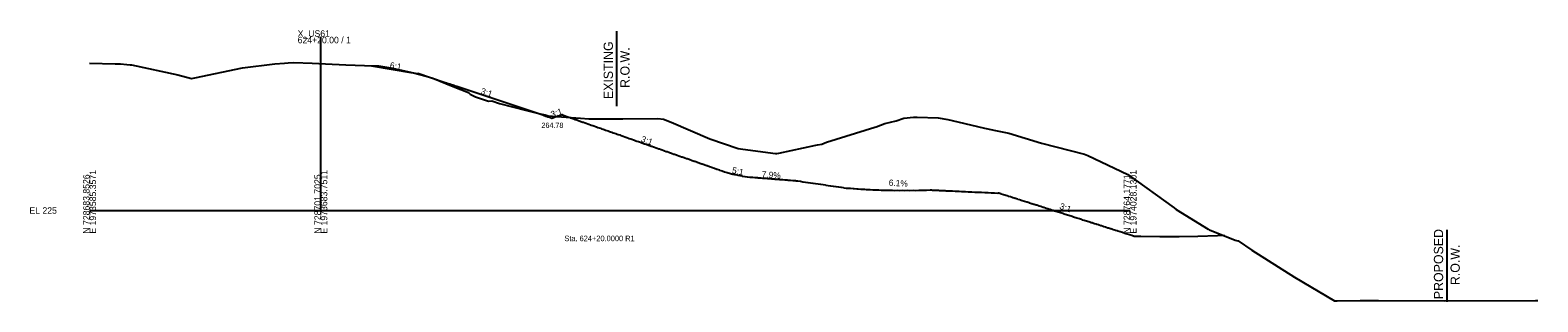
# Model space of a CAD drawing. Extents: x -26 to 630, y -39 to 9098.
# Drawn here: x -26 to 626, y 461 to 578 of the extents above; entities that cross this region are included whole.
import ezdxf

# ---------------------------------------------------------------- set-up
doc = ezdxf.new("R2010")
doc.units = 0
for name, color, linetype in [('CONST_DCH', 7, 'Continuous'), ('Default', 7, 'Continuous'), ('Draft_XS_Grid', 7, 'Continuous'), ('Draft_XS_Text', 7, 'Continuous'), ('DTM CONTOURS_MAJOR', 7, 'Continuous'), ('DTM_X_FLOW_ARROWS', 7, 'Continuous'), ('DTM_X_GROUND', 7, 'Continuous'), ('X_DTM_CONTOURS_MAJOR', 7, 'Continuous'), ('XS_CELL', 7, 'Continuous'), ('XS_P_GROUND', 7, 'Continuous'), ('XS_P_ROW', 7, 'Continuous'), ('XS_P_TX_DCH', 7, 'Continuous'), ('XS_P_TX_FS_BS', 7, 'Continuous'), ('XS_X_ROW', 7, 'Continuous')]:
    doc.layers.add(name, color=color, linetype=linetype)

msp = doc.modelspace()

# ---------------------------------------------------------------- linework, layer by layer
at = {"layer": 'DTM_X_GROUND'}
msp.add_lwpolyline([(0, 563.66), (11.1, 563.34), (13.43, 563.27), (16.14, 563.05), (17.6, 562.92), (18.16, 562.86), (38.23, 558.55), (44.07, 557.03), (45.47, 557.34), (66.13, 561.58), (80.12, 563.28), (84.36, 563.68), (85.9, 563.74), (88.33, 563.84), (96.23, 563.57), (102.11, 563.36), (110.84, 562.96), (122.88, 562.41), (123.55, 562.45), (125.17, 562.51), (130.34, 561.53), (140.05, 559.47), (145.65, 557.95), (148.53, 557.16), (157.2, 553.58), (163.95, 550.88), (164.61, 550.26), (166.94, 549.06), (172.54, 547.24), (174.02, 547.39), (177.3, 546.24), (188.5, 543.35), (194.95, 541.78), (197.02, 541.35), (198.38, 540.8), (202.11, 540.54), (212.35, 539.83), (215.89, 539.57), (223.5, 539.54), (226.67, 539.6), (227.21, 539.54), (230.69, 539.6), (245.81, 539.77), (248.27, 539.36), (251.61, 538.09), (268.33, 531), (280.45, 526.82), (281.46, 526.69), (291.23, 525.37), (296.62, 524.67), (297.28, 524.57), (298.08, 524.81), (314.15, 528.25), (314.84, 528.29), (316.73, 528.66), (318.77, 529.53), (339.61, 536.02), (340.19, 536.17), (343.92, 537.62), (348.86, 538.67), (352.14, 539.81), (356.33, 540.26), (357.98, 540.35), (367.03, 539.99), (367.03, 539.99), (371.19, 539.26), (375.53, 538.32), (387.04, 535.56), (387.73, 535.42), (391.84, 534.55), (397.54, 533.33), (411.74, 529.05), (430.32, 524.26), (431.77, 523.79), (449, 515.57), (469.04, 501.19), (470.02, 500.38), (483.78, 491.87), (484.27, 491.66), (484.35, 491.63), (495.47, 487.24), (496.65, 486.89), (496.75, 486.87), (502.68, 482.9), (521.09, 471.19), (538.46, 460.96), (539.62, 460.98), (549.52, 461.16), (557.4, 461.07), (585.97, 460.96), (625.4, 461.19), (626.37, 461.12)], dxfattribs=at)
at = {"layer": 'XS_CELL'}
for p, q in [((100, 500), (100, 575)), ((0, 500), (100, 500)), ((100, 500), (450, 500))]:
    msp.add_line(p, q, dxfattribs=at)
at = {"layer": 'XS_P_GROUND'}
for points in [[(122, 562.45), (138.95, 559.63), (142, 559.12)], [(204.48, 541.28), (204.44, 541.26), (203.26, 540.87), (201.88, 540.41), (201.78, 540.38), (200.32, 539.89), (200.07, 539.81), (200, 539.78), (199.22, 540.04), (199.11, 540.08), (198.3, 540.35), (198.26, 540.36), (197.95, 540.47), (197.92, 540.48), (197.65, 540.57), (197.63, 540.57), (197.4, 540.65), (197.39, 540.66), (197.19, 540.72), (197.17, 540.73), (197, 540.79), (196.98, 540.79), (196.83, 540.84), (196.82, 540.84), (196.68, 540.89), (196.63, 540.91), (196, 541.12), (158.78, 553.52), (158.75, 553.53), (158.16, 553.73), (158.13, 553.74), (157.59, 553.92), (157.57, 553.93), (157.07, 554.09), (157.05, 554.1), (156.6, 554.25), (156.57, 554.26), (156.15, 554.4), (156.13, 554.41), (155.75, 554.54), (155.69, 554.55), (154.68, 554.89), (154.67, 554.89), (154.4, 554.98), (153.79, 555.19), (142, 559.12)], [(204.48, 541.28), (204.56, 541.25), (204.56, 541.25), (205.66, 540.87), (205.71, 540.85), (206.75, 540.49), (206.86, 540.45), (207.85, 540.1), (208, 540.05), (208.94, 539.72), (209.13, 539.65), (210.03, 539.34), (210.26, 539.26), (211.13, 538.95), (211.38, 538.86), (212.22, 538.57), (212.51, 538.47), (213.32, 538.19), (213.63, 538.08), (214.41, 537.8), (214.76, 537.68), (215.51, 537.42), (215.88, 537.29), (216.6, 537.04), (217, 536.9), (217.7, 536.65), (218.12, 536.51), (218.79, 536.27), (219.24, 536.12), (219.89, 535.89), (220.36, 535.72), (220.98, 535.5), (221.47, 535.33), (222.08, 535.12), (222.59, 534.94), (223.17, 534.74), (223.71, 534.55), (224.27, 534.35), (224.82, 534.16), (225.36, 533.97), (225.94, 533.77), (226.46, 533.59), (227.05, 533.38), (227.55, 533.21), (228.16, 532.99), (228.65, 532.82), (229.28, 532.6), (229.74, 532.44), (230.39, 532.21), (230.83, 532.06), (231.5, 531.82), (231.93, 531.67), (232.35, 531.52), (233.02, 531.29), (233.44, 531.14), (234.12, 530.91), (234.53, 530.76), (235.21, 530.52), (235.62, 530.38), (236.31, 530.14), (236.71, 530), (237.4, 529.76), (237.8, 529.62), (238.5, 529.37), (238.89, 529.23), (239.59, 528.99), (239.98, 528.85), (240.69, 528.61), (241.07, 528.47), (241.78, 528.22), (242.16, 528.09), (242.88, 527.84), (243.25, 527.71), (243.97, 527.46), (244.34, 527.33), (245.07, 527.07), (245.43, 526.95), (246.16, 526.69), (246.52, 526.57), (247.26, 526.31), (247.61, 526.18), (248.35, 525.92), (248.69, 525.8), (249.45, 525.54), (249.78, 525.42), (250.54, 525.16), (250.87, 525.04), (251.63, 524.77), (251.96, 524.66), (252.73, 524.39), (253.04, 524.28), (253.82, 524.01), (254.13, 523.9), (254.92, 523.63), (255.22, 523.52), (256.01, 523.24), (256.3, 523.14), (257.11, 522.86), (257.39, 522.76), (258.2, 522.48), (258.47, 522.38), (259.3, 522.09), (259.56, 522), (260.39, 521.71), (260.64, 521.62), (261.49, 521.33), (261.71, 521.25), (262.58, 520.94), (262.79, 520.87), (263.68, 520.56), (263.87, 520.49), (264.77, 520.18), (264.95, 520.11), (265.87, 519.79), (266.03, 519.74), (266.96, 519.41), (267.11, 519.36), (268.06, 519.03), (268.19, 518.98), (269.15, 518.64), (269.27, 518.6), (270.25, 518.26), (270.34, 518.23), (271.34, 517.88), (271.42, 517.85), (272.43, 517.49), (272.5, 517.47), (273.53, 517.11), (273.58, 517.09), (274.62, 516.73), (274.65, 516.72), (275.72, 516.34), (275.73, 516.34), (276.17, 516.19), (276.81, 516.05), (277.68, 515.86), (277.91, 515.81), (278.21, 515.75), (279, 515.58), (279.5, 515.47), (280.1, 515.34), (280.54, 515.25), (281.19, 515.11), (282.07, 514.92), (282.29, 514.88), (283.35, 514.65), (283.38, 514.64), (283.54, 514.61)], [(283.54, 514.61), (284.48, 514.53), (284.53, 514.53), (285.57, 514.45), (285.68, 514.44), (286.67, 514.36), (286.83, 514.35), (287.76, 514.27), (287.98, 514.26), (288.86, 514.19), (289.13, 514.17), (289.95, 514.1), (290.28, 514.08), (291.05, 514.02), (291.44, 513.98), (292.14, 513.93), (292.59, 513.89), (293.23, 513.84), (293.74, 513.8), (294.33, 513.76), (294.89, 513.71), (295.42, 513.67), (296.04, 513.62), (296.52, 513.58), (297.19, 513.53), (297.61, 513.5), (298.35, 513.44), (298.71, 513.41), (299.5, 513.35), (299.8, 513.33), (300.65, 513.26), (300.9, 513.24), (301.8, 513.17), (301.99, 513.15), (302.95, 513.08), (303.09, 513.07), (304.11, 512.99), (304.18, 512.98), (305.26, 512.9), (305.28, 512.89), (305.66, 512.86), (306.37, 512.76), (306.37, 512.76), (307.45, 512.6), (307.47, 512.6), (308.54, 512.44), (308.56, 512.44), (309.62, 512.28), (309.66, 512.28), (310.71, 512.12), (310.75, 512.12), (311.79, 511.97), (311.85, 511.96), (312.88, 511.81), (312.94, 511.8), (313.97, 511.65), (314.03, 511.64), (315.05, 511.49), (315.13, 511.48), (316.14, 511.33), (316.22, 511.32), (317.22, 511.17), (317.32, 511.16), (318.31, 511.01), (318.41, 510.99), (319.4, 510.85), (319.51, 510.83), (320.48, 510.69), (320.6, 510.67), (321.57, 510.53), (321.7, 510.51), (322.71, 510.37), (322.79, 510.35), (322.93, 510.33), (323.89, 510.19), (324.04, 510.17), (324.98, 510.03), (325.14, 510.01), (326.08, 509.87), (326.25, 509.85), (327.17, 509.71), (327.21, 509.71), (327.4, 509.68), (327.73, 509.67), (328.64, 509.58), (329.09, 509.57), (330.23, 509.46), (330.73, 509.45), (331.85, 509.34), (332.39, 509.34), (333.5, 509.24), (334.09, 509.23), (335.19, 509.14), (335.84, 509.13), (336.92, 509.05), (337.63, 509.05), (338.69, 508.97), (339.46, 508.97), (340.5, 508.89), (341.34, 508.9), (342.37, 508.83), (343.28, 508.84), (344.28, 508.78), (345.27, 508.79), (346.25, 508.73), (347.33, 508.75), (348.27, 508.7), (349.45, 508.72), (350.36, 508.68), (351.65, 508.71), (352.52, 508.68), (353.92, 508.71), (354.75, 508.68), (356.27, 508.73), (357.06, 508.7), (358.72, 508.76), (359.46, 508.74), (361.26, 508.8), (361.95, 508.79), (363.6, 508.86), (364.14, 508.85), (364.22, 508.85), (364.36, 508.84), (364.84, 508.82), (365.78, 508.77), (366.24, 508.75), (367.2, 508.71), (367.64, 508.69), (368.63, 508.64), (369.03, 508.62), (370.05, 508.58), (370.43, 508.56), (371.47, 508.51), (371.83, 508.49), (372.9, 508.44), (373.23, 508.43), (374.32, 508.38), (374.63, 508.36), (375.74, 508.31), (376.03, 508.3), (377.17, 508.25), (377.43, 508.24), (378.59, 508.18), (378.82, 508.17), (380.02, 508.12), (380.22, 508.11), (381.44, 508.05), (381.62, 508.04), (382.86, 507.98), (383.02, 507.98), (384.29, 507.92), (384.42, 507.91), (385.71, 507.85), (385.82, 507.85), (387.13, 507.79), (387.23, 507.78), (388.56, 507.72), (388.63, 507.72), (389.98, 507.65), (390.03, 507.65), (391.4, 507.59), (391.43, 507.59), (392.83, 507.52), (392.83, 507.52), (392.95, 507.52)], [(490.9, 489.24), (487.85, 489.1), (487.8, 489.1), (479.35, 488.83), (471.21, 488.68), (471.07, 488.68), (462.98, 488.65), (462.89, 488.65), (454.71, 488.75), (454.67, 488.75), (451.82, 488.84), (451.81, 488.84), (450.83, 489.15), (450.8, 489.16), (449.81, 489.48), (449.79, 489.48), (448.79, 489.8), (448.78, 489.8), (448.19, 489.99), (447.77, 490.12), (447.76, 490.13), (446.76, 490.44), (446.71, 490.46), (445.75, 490.76), (445.67, 490.79), (444.74, 491.08), (444.71, 491.09), (444.49, 491.16), (444.39, 491.19), (443.73, 491.4), (443.71, 491.41), (443.6, 491.45), (443.46, 491.49), (442.72, 491.72), (442.54, 491.78), (441.71, 492.04), (441.5, 492.11), (440.7, 492.37), (440.46, 492.44), (439.69, 492.69), (439.43, 492.77), (438.68, 493.01), (438.39, 493.1), (437.67, 493.33), (437.36, 493.43), (436.66, 493.65), (436.33, 493.75), (435.65, 493.97), (435.29, 494.08), (434.64, 494.29), (434.26, 494.41), (433.63, 494.61), (433.23, 494.74), (432.62, 494.93), (432.2, 495.06), (431.61, 495.25), (431.17, 495.39), (430.6, 495.57), (430.14, 495.72), (429.59, 495.89), (429.11, 496.04), (428.58, 496.21), (428.09, 496.37), (427.57, 496.53), (427.06, 496.69), (426.56, 496.85), (426.03, 497.02), (425.55, 497.17), (425.01, 497.34), (424.54, 497.49), (423.98, 497.67), (423.53, 497.81), (422.96, 498), (422.52, 498.13), (421.93, 498.32), (421.51, 498.45), (420.91, 498.64), (420.5, 498.78), (419.89, 498.97), (419.49, 499.1), (418.86, 499.29), (418.48, 499.42), (417.84, 499.62), (417.47, 499.74), (417.39, 499.76), (417.34, 499.78), (416.77, 499.96), (416.46, 500.06), (415.8, 500.27), (415.45, 500.38), (414.78, 500.59), (414.44, 500.7), (413.75, 500.92), (413.43, 501.02), (412.73, 501.24), (412.42, 501.34), (411.7, 501.57), (411.41, 501.66), (410.67, 501.89), (410.4, 501.98), (409.63, 502.23), (409.39, 502.3), (408.58, 502.56), (408.38, 502.62), (407.54, 502.89), (407.37, 502.94), (406.49, 503.22), (406.36, 503.26), (405.44, 503.55), (405.35, 503.58), (404.4, 503.89), (404.34, 503.9), (403.35, 504.22), (403.33, 504.22), (402.92, 504.35), (402.57, 504.46), (402.45, 504.5), (402.32, 504.54), (401.5, 504.8), (401.31, 504.86), (400.53, 505.11), (400.3, 505.19), (399.85, 505.33), (399.29, 505.51), (399.01, 505.59), (398.28, 505.83), (397.43, 506.09), (397.27, 506.15), (396.89, 506.27), (396.26, 506.47), (395.79, 506.62), (395.25, 506.79), (395.23, 506.79), (394.24, 507.11), (394.08, 507.16), (393.23, 507.43), (393.13, 507.46), (393.13, 507.46), (392.95, 507.52)]]:
    msp.add_lwpolyline(points, dxfattribs=at)
at = {"layer": 'XS_P_ROW'}
msp.add_line((587, 491.59), (587, 460.58), dxfattribs=at)
at = {"layer": 'XS_X_ROW'}
msp.add_line((228, 545), (228, 577.48), dxfattribs=at)

# ---------------------------------------------------------------- texts
at = {"layer": 'CONST_DCH'}
for p in [(204.48, 541.28), (283.54, 514.61), (283.54, 514.61), (305.66, 512.86)]:
    msp.add_text('X', height=0.001, dxfattribs=at).set_placement(p)
at = {"layer": 'Default'}
for p in [(199.96, 539.72), (199.96, 539.72), (227.29, 539.49)]:
    msp.add_text('X', height=0.12, dxfattribs=at).set_placement(p)
at = {"layer": 'Draft_XS_Grid'}
msp.add_text('-', height=0.0001, dxfattribs=at).set_placement((0, 500))
at = {"layer": 'Draft_XS_Text'}
msp.add_text('Sta. 624+20.0000 R1', height=2.4, dxfattribs=at).set_placement((205.34, 486.75))
at = {"layer": 'DTM CONTOURS_MAJOR'}
msp.add_text('X', height=0.001, dxfattribs=at).set_placement((200, 539.78))
at = {"layer": 'DTM_X_FLOW_ARROWS'}
msp.add_text('X', height=0.001, dxfattribs=at).set_placement((276.17, 516.19))
at = {"layer": 'X_DTM_CONTOURS_MAJOR'}
for p in [(122, 562.45), (142, 559.12)]:
    msp.add_text('X', height=0.001, dxfattribs=at).set_placement(p)
at = {"layer": 'XS_CELL'}
for s, p in [('X_US61', (90, 575)), ('624+20.00 / 1', (90, 572.2)), ('EL 225', (-26, 498.6))]:
    msp.add_text(s, height=2.8, dxfattribs=at).set_placement(p)
for s, p in [('N 728683.8526', (0, 490)), ('E 1973585.3571', (2.8, 490)), ('N 728701.7025', (100, 490)), ('E 1973683.7511', (102.8, 490)), ('N 728764.1771', (450, 490)), ('E 1974028.1301', (452.8, 490))]:
    msp.add_text(s, height=2.8, rotation=90, dxfattribs=at).set_placement(p)
at = {"layer": 'XS_P_ROW'}
for s, p in [('EXISTING', (226.34, 548.08)), ('R.O.W.', (233.54, 552.92)), ('PROPOSED', (585.41, 461.7)), ('R.O.W.', (592.61, 467.77))]:
    msp.add_text(s, height=4, rotation=90, dxfattribs=at).set_placement(p)
at = {"layer": 'XS_P_TX_DCH'}
msp.add_text('264.78', height=2.25, dxfattribs=at).set_placement((195.44, 535.67))
at = {"layer": 'XS_P_TX_FS_BS'}
for s, rotation, p in [('6:1', 350.53768, (129.72, 561.47)), ('3:1', 341.56505, (168.92, 550.46)), ('3:1', 18.43367, (199.97, 540.09)), ('3:1', 340.70774, (238.26, 529.78)), ('5:1', 347.89889, (277.67, 516.17)), ('7.9%', 355.49667, (290.61, 514.35)), ('6.1%', 356.49434, (345.58, 510.72)), ('3:1', 340.70774, (419.26, 500.78))]:
    msp.add_text(s, height=2.7, rotation=rotation, dxfattribs=at).set_placement(p)

doc.saveas('drawing.dxf')
